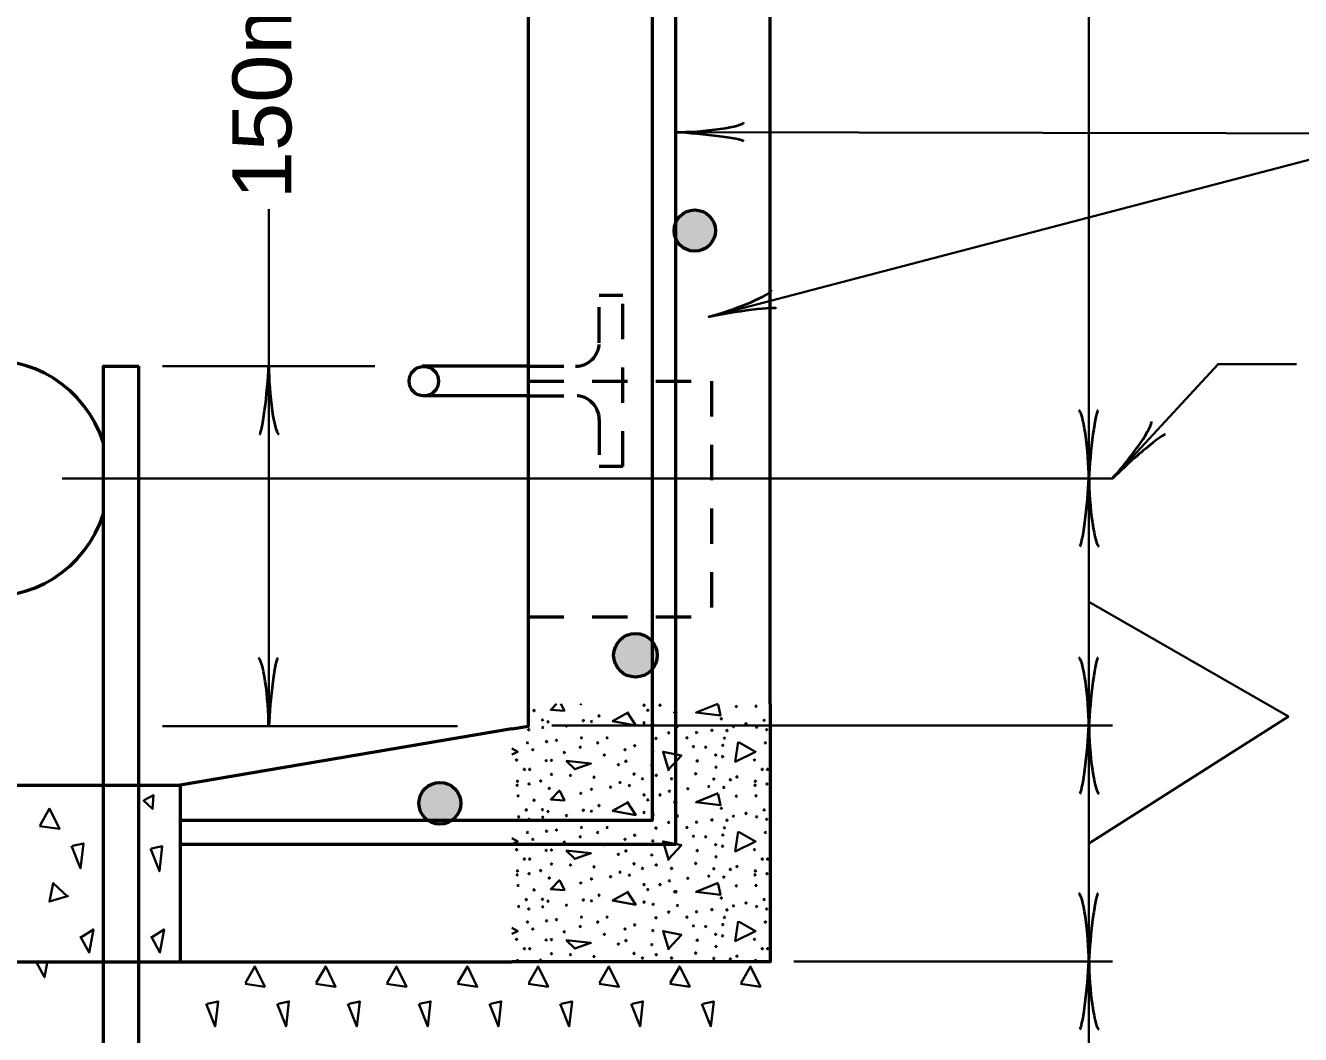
# Model space of a CAD drawing. Extents: x 918 to 1774, y -8 to 536.
# Drawn here: x 1102.6 to 1167.4, y 142.4 to 193.7 of the extents above; entities that cross this region are included whole.
import ezdxf

# ---------------------------------------------------------------- set-up
doc = ezdxf.new("R2010")
doc.units = 0
doc.header["$LTSCALE"] = 1.2
doc.linetypes.add('SHORT_DASHED', pattern=[2.7, 1.5, -1.2])
doc.layers.add('1', color=7, linetype='Continuous', lineweight=35)

msp = doc.modelspace()

# ---------------------------------------------------------------- hatches: boundary and pattern name
at = {"layer": '1'}
for points in [[(1135.54, 183.245, 1), (1137.641, 183.245, 1)], [(1132.465, 161.645, 1), (1134.682, 161.645, 1)], [(1122.568, 154.116, 1), (1124.692, 154.116, 1)]]:
    msp.add_hatch(color=256, dxfattribs=at).paths.add_polyline_path(points)

# ---------------------------------------------------------------- linework, layer by layer
at = {"layer": '1', "lineweight": 53}
for p, q in [((1128.128, 159.172), (1128.128, 198.122)), ((1140.428, 159.172), (1140.428, 198.122)), ((1108.328, 134.643), (1108.328, 176.343)), ((1128.128, 176.343), (1122.727, 176.343)), ((1128.128, 174.843), (1122.727, 174.843)), ((1127.291, 157.902), (1110.428, 155.043)), ((1091.227, 155.043), (1110.428, 155.043)), ((1110.428, 155.043), (1110.428, 146.043)), ((1072.952, 146.043), (1127.291, 146.043))]:
    msp.add_line(p, q, dxfattribs=at)
at = {"layer": '1'}
for p, q in [((1114.928, 184.342), (1114.928, 158.043)), ((1120.328, 176.343), (1109.528, 176.343)), ((1104.428, 170.643), (1157.828, 170.643)), ((1124.528, 158.043), (1109.528, 158.043)), ((1129.328, 158.067), (1157.828, 158.067)), ((1103.2, 146.086), (1103.078, 146.007)), ((1141.628, 146.075), (1157.828, 146.075))]:
    msp.add_line(p, q, dxfattribs=at)
at = {"layer": '1', "linetype": 'SHORT_DASHED', "lineweight": 53}
for p, q in [((1131.727, 177.543), (1131.727, 179.943)), ((1128.128, 176.343), (1130.528, 176.343)), ((1128.128, 175.593), (1137.439, 175.593)), ((1137.439, 175.593), (1137.439, 163.593)), ((1128.128, 174.843), (1130.528, 174.843)), ((1131.727, 173.643), (1131.727, 171.243)), ((1132.928, 171.243), (1131.727, 171.243)), ((1128.128, 163.593), (1137.439, 163.593))]:
    msp.add_line(p, q, dxfattribs=at)
at = {"layer": '1'}
for points in [[(1156.628, 235.047), (1156.628, 170.643), (1156.628, 158.067), (1156.628, 146.075), (1156.628, 108.575)], [(1137.277, 178.85), (1172.928, 188.177), (1135.628, 188.246)], [(1157.828, 170.643), (1163.195, 176.452), (1167.189, 176.452)], [(1156.628, 164.355), (1166.77, 158.522), (1156.628, 152.071)], [(1129.552, 159.172), (1129.265, 158.87), (1129.961, 158.822), (1129.786, 159.172)], [(1137.76, 159.172), (1136.657, 158.726), (1137.905, 158.582), (1137.785, 159.134)], [(1133.201, 158.726), (1132.409, 158.294), (1133.585, 158.078), (1133.153, 158.75)], [(1127.291, 156.902), (1127.585, 156.734), (1127.291, 156.591)], [(1138.841, 157.214), (1139.681, 156.734), (1138.649, 156.23), (1138.793, 157.238)], [(1135.265, 155.774), (1134.977, 156.734), (1135.913, 156.542), (1135.241, 155.822)], [(1108.545, 154.282), (1109.025, 153.826), (1109.073, 154.522), (1108.593, 154.282)], [(1129.721, 154.79), (1129.265, 154.31), (1129.961, 154.262), (1129.721, 154.742)], [(1137.785, 154.622), (1136.657, 154.166), (1137.905, 154.022), (1137.785, 154.574)], [(1103.3, 153.007), (1103.78, 153.847), (1104.284, 152.815), (1103.276, 152.959)], [(1133.201, 154.166), (1132.409, 153.734), (1133.585, 153.518), (1133.153, 154.19)], [(1127.291, 152.342), (1127.585, 152.174), (1127.291, 152.031)], [(1138.841, 152.654), (1139.681, 152.174), (1138.649, 151.67), (1138.793, 152.678)], [(1104.908, 151.951), (1105.364, 150.799), (1105.508, 152.071), (1104.956, 151.951)], [(1108.917, 151.808), (1109.373, 150.656), (1109.517, 151.928), (1108.965, 151.808)], [(1135.265, 151.214), (1134.977, 152.174), (1135.913, 151.982), (1135.241, 151.262)], [(1104.74, 149.406), (1103.78, 149.119), (1103.972, 150.055), (1104.692, 149.382)], [(1129.721, 150.23), (1129.265, 149.75), (1129.961, 149.702), (1129.721, 150.182)], [(1137.785, 150.062), (1136.657, 149.606), (1137.905, 149.462), (1137.785, 150.014)], [(1133.201, 149.606), (1132.409, 149.174), (1133.585, 148.958), (1133.153, 149.63)], [(1138.841, 148.094), (1139.681, 147.614), (1138.649, 147.11), (1138.793, 148.118)], [(1105.364, 147.319), (1105.796, 146.526), (1106.012, 147.703), (1105.34, 147.27)], [(1108.964, 147.319), (1109.396, 146.526), (1109.612, 147.703), (1108.94, 147.27)], [(1127.291, 147.782), (1127.585, 147.614), (1127.291, 147.471)], [(1135.265, 146.654), (1134.977, 147.614), (1135.913, 147.422), (1135.241, 146.702)], [(1103.102, 146.055), (1103.534, 145.263), (1103.685, 146.086)], [(1113.746, 144.975), (1114.226, 145.815), (1114.73, 144.783), (1113.722, 144.927)], [(1117.346, 144.975), (1117.826, 145.815), (1118.33, 144.783), (1117.322, 144.927)], [(1120.946, 144.975), (1121.426, 145.815), (1121.93, 144.783), (1120.922, 144.927)], [(1124.546, 144.975), (1125.026, 145.815), (1125.53, 144.783), (1124.522, 144.927)], [(1128.146, 144.975), (1128.626, 145.815), (1129.13, 144.783), (1128.122, 144.927)], [(1131.746, 144.975), (1132.226, 145.815), (1132.73, 144.783), (1131.722, 144.927)], [(1135.346, 144.975), (1135.826, 145.815), (1136.33, 144.783), (1135.322, 144.927)], [(1138.946, 144.975), (1139.426, 145.815), (1139.93, 144.783), (1138.922, 144.927)], [(1111.754, 143.919), (1112.21, 142.767), (1112.354, 144.039), (1111.802, 143.919)], [(1115.354, 143.919), (1115.81, 142.767), (1115.954, 144.039), (1115.402, 143.919)], [(1118.954, 143.919), (1119.41, 142.767), (1119.554, 144.039), (1119.002, 143.919)], [(1122.554, 143.919), (1123.01, 142.767), (1123.154, 144.039), (1122.602, 143.919)], [(1126.154, 143.919), (1126.61, 142.767), (1126.754, 144.039), (1126.202, 143.919)], [(1129.754, 143.919), (1130.21, 142.767), (1130.354, 144.039), (1129.802, 143.919)], [(1133.354, 143.919), (1133.81, 142.767), (1133.954, 144.039), (1133.402, 143.919)], [(1136.954, 143.919), (1137.41, 142.767), (1137.554, 144.039), (1137.002, 143.919)]]:
    msp.add_lwpolyline(points, dxfattribs=at)
at = {"layer": '1', "lineweight": 53}
msp.add_lwpolyline([(1135.628, 152.043), (1135.628, 224.745), (1134.428, 224.745), (1134.428, 153.243), (1110.428, 153.243), (1110.428, 152.043)], close=True, dxfattribs=at)
at = {"layer": '1', "linetype": 'SHORT_DASHED', "lineweight": 53}
msp.add_lwpolyline([(1132.928, 171.243), (1132.928, 179.943), (1131.727, 179.943)], dxfattribs=at)
at = {"layer": '1', "lineweight": 53}
for points in [[(1106.528, 134.643), (1106.528, 176.343), (1108.328, 176.343)], [(1127.291, 157.902), (1128.128, 158.043), (1128.128, 159.172)], [(1140.428, 159.172), (1140.428, 146.043), (1127.291, 146.043)]]:
    msp.add_lwpolyline(points, dxfattribs=at)
at = {"layer": '1'}
for points in [[(1130.057, 156.278), (1131.305, 156.134), (1130.489, 155.846)], [(1130.057, 151.718), (1131.305, 151.574), (1130.489, 151.286)], [(1130.057, 147.158), (1131.305, 147.014), (1130.489, 146.726)]]:
    msp.add_lwpolyline(points, close=True, dxfattribs=at)
at = {"layer": '1', "lineweight": 53}
for centre, radius in [((1136.59, 183.245), 1.05), ((1122.812, 175.584), 0.75), ((1133.573, 161.645), 1.109), ((1123.63, 154.116), 1.062)]:
    msp.add_circle(centre, radius, dxfattribs=at)
at = {"layer": '1'}
for centre in [(1128.419, 158.83), (1134.01, 159.101), (1134.201, 158.846), (1134.822, 159.101), (1138.702, 159.037), (1139.704, 159.053), (1128.849, 158.353), (1129.128, 158.258), (1130.925, 158.321), (1131.339, 158.273), (1131.72, 158.56), (1134.011, 158.21), (1135.569, 158.735), (1135.633, 158.735), (1137.939, 158.417), (1139.195, 158.162), (1140.118, 158.337), (1128.149, 157.86), (1128.864, 157.971), (1130.066, 158.051), (1134.472, 158.098), (1135.267, 157.701), (1135.712, 158.035), (1136.682, 157.717), (1137.462, 157.828), (1138.225, 157.812), (1138.559, 158.019), (1139.736, 157.987), (1140.245, 157.86), (1128.085, 157.192), (1128.356, 156.842), (1129.055, 157.255), (1129.557, 157.319), (1130.766, 156.969), (1130.83, 157.446), (1131.657, 157.192), (1132.134, 157.446), (1133.04, 156.842), (1133.533, 157.048), (1134.615, 157.414), (1136.189, 157.446), (1136.523, 157.001), (1137.144, 156.969), (1138.018, 157.064), (1138.098, 157.43), (1140.181, 157.192), (1127.529, 156.317), (1129.032, 156.282), (1129.303, 156.301), (1129.955, 156.698), (1131.991, 156.571), (1133.088, 156.253), (1134.456, 156.762), (1136.714, 156.269), (1137.652, 156.571), (1138.002, 156.492), (1139.625, 156.317), (1127.926, 155.839), (1128.197, 155.839), (1129.303, 155.585), (1132.706, 156.078), (1133.502, 155.601), (1134.408, 156.046), (1136.635, 155.617), (1137.668, 155.951), (1140.022, 155.839), (1140.293, 155.839), (1127.56, 155.034), (1127.576, 155.235), (1128.165, 155.097), (1128.753, 155.251), (1130.273, 155.537), (1131.466, 155.442), (1132.309, 154.938), (1132.786, 155.171), (1133.263, 155.018), (1133.931, 155.362), (1134.631, 155.537), (1135.41, 155.362), (1137.303, 154.97), (1137.557, 155.346), (1138.066, 154.922), (1138.4, 155.314), (1138.734, 155.458), (1139.656, 155.034), (1139.672, 155.235), (1140.261, 155.097), (1127.608, 154.493), (1128.419, 154.27), (1129.192, 154.875), (1130.798, 154.62), (1131.339, 154.827), (1134.01, 154.541), (1134.201, 154.286), (1134.822, 154.541), (1135.299, 154.732), (1136.237, 154.859), (1138.702, 154.477), (1139.704, 154.493), (1128.022, 153.777), (1128.849, 153.793), (1129.128, 153.698), (1130.925, 153.761), (1131.339, 153.713), (1131.72, 154), (1134.011, 153.65), (1135.569, 154.175), (1135.633, 154.175), (1137.939, 153.857), (1139.195, 153.602), (1140.118, 153.777), (1127.64, 153.427), (1128.149, 153.3), (1128.864, 153.411), (1130.066, 153.491), (1134.472, 153.538), (1135.267, 153.141), (1135.712, 153.475), (1136.682, 153.157), (1137.462, 153.268), (1138.225, 153.252), (1138.559, 153.459), (1139.736, 153.427), (1140.245, 153.3), (1128.085, 152.632), (1129.055, 152.695), (1129.557, 152.759), (1130.766, 152.409), (1130.83, 152.886), (1131.657, 152.632), (1132.134, 152.886), (1133.533, 152.488), (1134.615, 152.854), (1136.189, 152.886), (1136.523, 152.441), (1137.144, 152.409), (1138.018, 152.504), (1138.098, 152.87), (1140.181, 152.632), (1127.529, 151.757), (1128.356, 152.282), (1129.032, 151.722), (1129.303, 151.741), (1129.955, 152.138), (1131.991, 152.011), (1133.04, 152.282), (1133.088, 151.693), (1134.456, 152.202), (1136.714, 151.709), (1137.652, 152.011), (1138.002, 151.932), (1139.625, 151.757), (1127.926, 151.279), (1128.197, 151.279), (1129.303, 151.025), (1132.706, 151.518), (1133.502, 151.041), (1134.408, 151.486), (1136.635, 151.057), (1137.668, 151.391), (1140.022, 151.279), (1140.293, 151.279), (1127.56, 150.474), (1127.576, 150.675), (1128.165, 150.537), (1128.753, 150.691), (1130.273, 150.977), (1131.466, 150.882), (1132.309, 150.378), (1132.786, 150.611), (1133.263, 150.458), (1133.931, 150.802), (1134.631, 150.977), (1135.41, 150.802), (1137.303, 150.41), (1137.557, 150.786), (1138.066, 150.362), (1138.4, 150.754), (1138.734, 150.898), (1139.656, 150.474), (1139.672, 150.675), (1140.261, 150.537), (1127.608, 149.933), (1129.192, 150.315), (1130.798, 150.06), (1131.339, 150.267), (1134.01, 149.981), (1134.201, 149.726), (1134.822, 149.981), (1135.299, 150.172), (1136.237, 150.299), (1138.702, 149.917), (1139.704, 149.933), (1128.022, 149.217), (1128.419, 149.71), (1128.849, 149.233), (1129.128, 149.138), (1130.925, 149.201), (1131.339, 149.153), (1131.72, 149.44), (1134.011, 149.09), (1135.569, 149.615), (1135.633, 149.615), (1137.939, 149.297), (1140.118, 149.217), (1127.64, 148.867), (1128.149, 148.74), (1128.864, 148.851), (1130.066, 148.931), (1134.472, 148.978), (1135.267, 148.581), (1135.712, 148.915), (1136.682, 148.597), (1137.462, 148.708), (1138.225, 148.692), (1138.559, 148.899), (1139.195, 149.042), (1139.736, 148.867), (1140.245, 148.74), (1128.085, 148.072), (1129.055, 148.135), (1129.557, 148.199), (1130.766, 147.849), (1130.83, 148.326), (1131.657, 148.072), (1132.134, 148.326), (1133.533, 147.928), (1134.615, 148.294), (1136.189, 148.326), (1136.523, 147.881), (1137.144, 147.849), (1138.018, 147.944), (1138.098, 148.31), (1140.181, 148.072), (1127.529, 147.197), (1128.356, 147.722), (1129.032, 147.162), (1129.303, 147.181), (1129.955, 147.578), (1131.991, 147.451), (1133.04, 147.722), (1133.088, 147.133), (1134.456, 147.642), (1136.714, 147.149), (1137.652, 147.451), (1138.002, 147.372), (1139.625, 147.197), (1127.926, 146.719), (1128.197, 146.719), (1132.706, 146.958), (1133.502, 146.481), (1134.408, 146.926), (1136.635, 146.497), (1137.668, 146.831), (1140.022, 146.719), (1140.293, 146.719), (1127.576, 146.115), (1128.753, 146.131), (1129.303, 146.465), (1130.273, 146.417), (1131.466, 146.322), (1133.931, 146.242), (1134.631, 146.417), (1135.41, 146.242), (1137.557, 146.226), (1138.4, 146.194), (1138.734, 146.338), (1139.672, 146.115)]:
    msp.add_circle(centre, 0.0318, dxfattribs=at)
at = {"layer": '1', "linetype": 'SHORT_DASHED', "lineweight": 53}
for centre, start, end in [((1130.528, 177.543), 270, 0), ((1130.528, 173.643), 0, 90)]:
    msp.add_arc(centre, 1.2, start, end, dxfattribs=at)
at = {"layer": '1', "lineweight": 53}
msp.add_arc((1100.802, 170.644), 6, 17.38217, 342.61783, dxfattribs=at)
at = {"layer": '1'}
for centre, start, end in [((1130.798, 159.18), 194.67944, 345.32056), ((1127.64, 157.987), 244.31226, 314.91884), ((1140.452, 156.842), 139.35432, 220.64568), ((1140.452, 152.282), 139.35432, 220.64568), ((1140.452, 147.722), 139.35432, 220.64568), ((1132.786, 146.051), 345.72609, 194.27391)]:
    msp.add_arc(centre, 0.0318, start, end, dxfattribs=at)
at = {"layer": '1', "lineweight": 40}
for centre, major_axis, ratio, start_param, end_param in [((1136.938, 188.575), (-2.143, -0.183), 0.122415, 0.896353, 3.141593), ((1136.938, 188.575), (-2.143, -0.183), 0.122415, 0.896353, 3.141593), ((1136.972, 187.989), (-2.107, 0.215), 0.07063, 3.140715, 5.41811), ((1136.972, 187.989), (-2.107, 0.215), 0.07063, 3.140715, 5.41811), ((1138.459, 179.502), (-2.026, -0.724), 0.122415, 0.896353, 3.141593), ((1138.459, 179.502), (-2.026, -0.724), 0.122415, 0.896353, 3.141593), ((1138.642, 178.944), (2.092, 0.33), 0.07063, 6.282307, 8.559703), ((1138.642, 178.944), (2.092, 0.33), 0.07063, 6.282307, 8.559703), ((1114.674, 174.999), (0.211, 2.108), 0.07063, 3.140715, 5.41811), ((1114.674, 174.999), (0.211, 2.108), 0.07063, 3.140715, 5.41811), ((1115.259, 175.034), (-0.187, 2.143), 0.122415, 0.896353, 3.141593), ((1115.259, 175.034), (-0.187, 2.143), 0.122415, 0.896353, 3.141593), ((1156.296, 171.953), (0.187, -2.143), 0.122415, 0.896353, 3.141593), ((1156.296, 171.953), (0.187, -2.143), 0.122415, 0.896353, 3.141593), ((1156.881, 171.988), (-0.211, -2.108), 0.07063, 3.140715, 5.41811), ((1156.881, 171.988), (-0.211, -2.108), 0.07063, 3.140715, 5.41811), ((1158.473, 171.83), (-1.317, -1.701), 0.122415, 0.896353, 3.141593), ((1158.927, 171.459), (1.585, 1.405), 0.07063, 6.282307, 8.559703), ((1156.374, 169.299), (0.211, 2.108), 0.07063, 3.140715, 5.41811), ((1156.374, 169.299), (0.211, 2.108), 0.07063, 3.140715, 5.41811), ((1156.959, 169.334), (-0.187, 2.143), 0.122415, 0.896353, 3.141593), ((1156.959, 169.334), (-0.187, 2.143), 0.122415, 0.896353, 3.141593), ((1114.596, 159.353), (0.187, -2.143), 0.122415, 0.896353, 3.141593), ((1115.181, 159.388), (-0.211, -2.108), 0.07063, 3.140715, 5.41811), ((1156.296, 159.377), (0.187, -2.143), 0.122415, 0.896353, 3.141593), ((1156.881, 159.412), (-0.211, -2.108), 0.07063, 3.140715, 5.41811), ((1156.374, 156.723), (0.211, 2.108), 0.07063, 3.140715, 5.41811), ((1156.374, 156.723), (0.211, 2.108), 0.07063, 3.140715, 5.41811), ((1156.959, 156.758), (-0.187, 2.143), 0.122415, 0.896353, 3.141593), ((1156.959, 156.758), (-0.187, 2.143), 0.122415, 0.896353, 3.141593), ((1156.296, 147.385), (0.187, -2.143), 0.122415, 0.896353, 3.141593), ((1156.296, 147.385), (0.187, -2.143), 0.122415, 0.896353, 3.141593), ((1156.881, 147.42), (-0.211, -2.108), 0.07063, 3.140715, 5.41811), ((1156.881, 147.42), (-0.211, -2.108), 0.07063, 3.140715, 5.41811), ((1156.374, 144.731), (0.211, 2.108), 0.07063, 3.140715, 5.41811), ((1156.374, 144.731), (0.211, 2.108), 0.07063, 3.140715, 5.41811), ((1156.959, 144.766), (-0.187, 2.143), 0.122415, 0.896353, 3.141593), ((1156.959, 144.766), (-0.187, 2.143), 0.122415, 0.896353, 3.141593)]:
    msp.add_ellipse(centre, major_axis=major_axis, ratio=ratio, start_param=start_param, end_param=end_param, dxfattribs=at)

# ---------------------------------------------------------------- texts
at = {"layer": '1', "width": 1.1}
msp.add_text('150mm', height=3, rotation=90, dxfattribs=at).set_placement((1116.081, 184.837))

doc.saveas('drawing.dxf')
